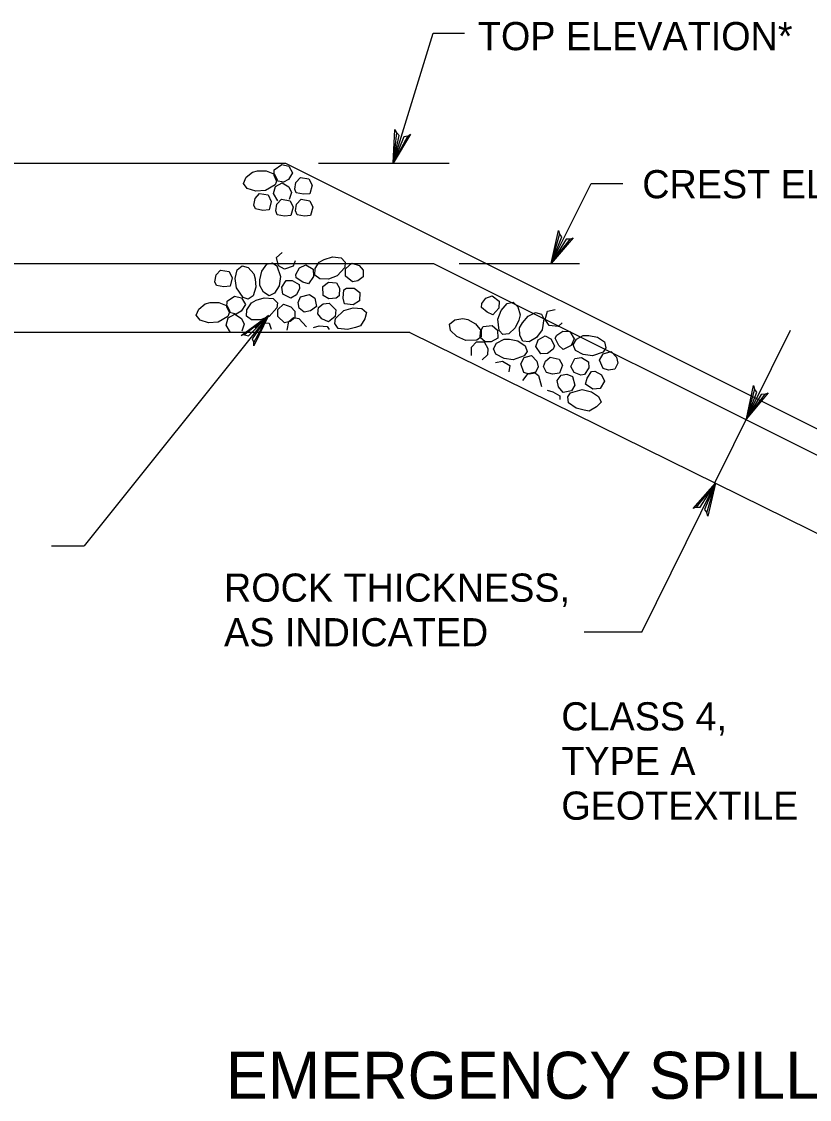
# Model space of a CAD drawing. Extents: x 636462 to 639890, y 299944 to 300538.
# Drawn here: x 637760.4 to 637844.1, y 300239.8 to 300354.4 of the extents above; entities that cross this region are included whole.
import ezdxf

# ---------------------------------------------------------------- set-up
doc = ezdxf.new("R2010")
doc.units = 0
doc.layers.add('Default', color=7, linetype='Continuous')

msp = doc.modelspace()

# ---------------------------------------------------------------- linework, layer by layer
at = {"layer": 'Default'}
for p, q in [((637799.86, 300339.34), (637804.11, 300353.17)), ((637804.11, 300353.17), (637807.46, 300353.17)), ((637706.06, 300339.34), (637788.44, 300339.34)), ((637788.44, 300339.34), (637929.75, 300268.68)), ((637791.92, 300339.34), (637805.8, 300339.34)), ((637784.24, 300337.85), (637784.93, 300338.41)), ((637784.93, 300338.41), (637785.44, 300338.53)), ((637785.44, 300338.53), (637786.38, 300338.54)), ((637786.38, 300338.54), (637787.26, 300338.17)), ((637787.22, 300338.05), (637787.24, 300338.66)), ((637787.24, 300338.66), (637788.03, 300339.21)), ((637788.03, 300339.21), (637788.77, 300339.03)), ((637789.19, 300338.32), (637788.75, 300337.63)), ((637788.77, 300339.03), (637789.19, 300338.32)), ((637783.96, 300337.18), (637784.24, 300337.85)), ((637784.37, 300336.65), (637783.96, 300337.18)), ((637787.33, 300337.06), (637786.29, 300336.46)), ((637787.49, 300337.48), (637787.22, 300338.05)), ((637787.26, 300338.17), (637787.55, 300337.61)), ((637787.55, 300337.61), (637787.33, 300337.06)), ((637787.36, 300336.89), (637788.08, 300337.28)), ((637788.2, 300337.32), (637787.49, 300337.48)), ((637788.08, 300337.28), (637788.77, 300336.85)), ((637788.75, 300337.63), (637788.2, 300337.32)), ((637789.41, 300336.59), (637789.52, 300337.31)), ((637789.52, 300337.31), (637790.01, 300337.83)), ((637790.01, 300337.83), (637790.92, 300337.68)), ((637790.92, 300337.68), (637791.25, 300337)), ((637816.66, 300328.69), (637820.91, 300337.19)), ((637820.91, 300337.19), (637824.26, 300337.19)), ((637785.27, 300336.39), (637784.37, 300336.65)), ((637785.19, 300335.6), (637785.68, 300336.13)), ((637786.29, 300336.46), (637785.27, 300336.39)), ((637785.68, 300336.13), (637786.59, 300335.98)), ((637786.59, 300335.98), (637786.92, 300335.29)), ((637787.16, 300336.14), (637787.36, 300336.89)), ((637787.6, 300335.36), (637787.16, 300336.14)), ((637788.77, 300336.85), (637789.05, 300336.23)), ((637789.05, 300336.23), (637788.81, 300335.5)), ((637789.57, 300336.19), (637789.41, 300336.59)), ((637790.35, 300336.05), (637789.57, 300336.19)), ((637791.01, 300336.11), (637790.35, 300336.05)), ((637791.25, 300337), (637791.01, 300336.11)), ((637785.08, 300334.88), (637785.19, 300335.6)), ((637785.24, 300334.49), (637785.08, 300334.88)), ((637786.92, 300335.29), (637786.68, 300334.4)), ((637787.4, 300334.27), (637787.51, 300334.99)), ((637787.51, 300334.99), (637788, 300335.51)), ((637788, 300335.51), (637788.91, 300335.36)), ((637788.91, 300335.36), (637789.24, 300334.68)), ((637789.5, 300334.27), (637789.61, 300334.99)), ((637789.61, 300334.99), (637790.1, 300335.51)), ((637790.1, 300335.51), (637791.01, 300335.36)), ((637791.01, 300335.36), (637791.34, 300334.68)), ((637786.02, 300334.34), (637785.24, 300334.49)), ((637786.68, 300334.4), (637786.02, 300334.34)), ((637787.56, 300333.87), (637787.4, 300334.27)), ((637788.34, 300333.73), (637787.56, 300333.87)), ((637789, 300333.79), (637788.34, 300333.73)), ((637789.24, 300334.68), (637789, 300333.79)), ((637789.66, 300333.87), (637789.5, 300334.27)), ((637790.44, 300333.73), (637789.66, 300333.87)), ((637791.1, 300333.79), (637790.44, 300333.73)), ((637791.34, 300334.68), (637791.1, 300333.79)), ((637787.48, 300329.31), (637788.09, 300329.86)), ((637787.68, 300328.45), (637787.48, 300329.31)), ((637792.02, 300328.84), (637792.55, 300329.13)), ((637792.55, 300329.13), (637793.44, 300329.4)), ((637793.44, 300329.4), (637794.34, 300329.3)), ((637794.34, 300329.3), (637794.77, 300328.83)), ((637684.74, 300328.68), (637804.15, 300328.68)), ((637781.05, 300327.47), (637781.54, 300327.99)), ((637781.54, 300327.99), (637782.45, 300327.84)), ((637783.09, 300327.08), (637783.31, 300328.02)), ((637783.31, 300328.02), (637783.81, 300328.44)), ((637783.81, 300328.44), (637784.47, 300328.26)), ((637784.47, 300328.26), (637785.08, 300327.59)), ((637785.9, 300327.87), (637786.43, 300328.61)), ((637786.43, 300328.61), (637787.05, 300328.75)), ((637787.05, 300328.75), (637787.51, 300328.44)), ((637787.51, 300328.44), (637787.89, 300327.3)), ((637788.34, 300328.07), (637787.68, 300328.45)), ((637789.26, 300328.42), (637788.34, 300328.07)), ((637789.44, 300328.97), (637789.26, 300328.42)), ((637789.54, 300327.53), (637789.91, 300328.24)), ((637789.91, 300328.24), (637790.6, 300328.54)), ((637790.6, 300328.54), (637791.37, 300328.08)), ((637791.37, 300328.08), (637791.42, 300327.29)), ((637791.55, 300327.45), (637791.59, 300328.15)), ((637791.59, 300328.15), (637792.02, 300328.84)), ((637794.72, 300328.27), (637793.92, 300327.38)), ((637794.77, 300328.83), (637794.72, 300328.27)), ((637794.8, 300327.36), (637794.81, 300328.12)), ((637794.81, 300328.12), (637795.47, 300328.72)), ((637795.47, 300328.72), (637796.24, 300328.46)), ((637796.24, 300328.46), (637796.67, 300327.99)), ((637796.67, 300327.99), (637796.69, 300327.27)), ((637804.16, 300328.69), (637929.74, 300265.89)), ((637806.87, 300328.69), (637819.67, 300328.69)), ((637780.94, 300326.75), (637781.05, 300327.47)), ((637781.09, 300326.35), (637780.94, 300326.75)), ((637782.45, 300327.84), (637782.78, 300327.16)), ((637782.78, 300327.16), (637782.54, 300326.27)), ((637783.23, 300326.1), (637783.09, 300327.08)), ((637785.08, 300327.59), (637785.22, 300327.06)), ((637785.22, 300327.06), (637785.28, 300326.16)), ((637785.7, 300326.96), (637785.9, 300327.87)), ((637785.7, 300326.36), (637785.7, 300326.96)), ((637787.89, 300327.3), (637787.75, 300326.32)), ((637788.03, 300326.16), (637788.5, 300326.9)), ((637788.5, 300326.9), (637789.15, 300326.89)), ((637789.15, 300326.89), (637789.87, 300326.44)), ((637789.55, 300327.18), (637789.54, 300327.53)), ((637790.26, 300326.7), (637789.55, 300327.18)), ((637791.42, 300327.29), (637790.87, 300326.52)), ((637792.07, 300327.06), (637791.55, 300327.45)), ((637792.99, 300327.03), (637792.07, 300327.06)), ((637793.92, 300327.38), (637792.99, 300327.03)), ((637795.56, 300326.73), (637794.8, 300327.36)), ((637796.13, 300326.85), (637795.56, 300326.73)), ((637796.69, 300327.27), (637796.13, 300326.85)), ((637781.88, 300326.21), (637781.09, 300326.35)), ((637782.54, 300326.27), (637781.88, 300326.21)), ((637783.92, 300325.09), (637783.23, 300326.1)), ((637785.28, 300326.16), (637785, 300325.25)), ((637786.09, 300325.65), (637785.7, 300326.36)), ((637786.68, 300325.27), (637786.09, 300325.65)), ((637787.75, 300326.32), (637787.27, 300325.53)), ((637788.15, 300325.44), (637788.03, 300326.16)), ((637789.91, 300326.04), (637789.6, 300325.36)), ((637789.87, 300326.44), (637789.91, 300326.04)), ((637790.87, 300326.52), (637790.26, 300326.7)), ((637792.41, 300326.25), (637792.98, 300326.71)), ((637792.43, 300325.3), (637792.41, 300326.25)), ((637792.98, 300326.71), (637793.86, 300326.65)), ((637793.86, 300326.65), (637794.17, 300326.08)), ((637794.17, 300326.08), (637794.13, 300325.24)), ((637794.55, 300325.02), (637794.61, 300325.88)), ((637794.61, 300325.88), (637794.91, 300326.06)), ((637794.91, 300326.06), (637795.72, 300326.08)), ((637795.72, 300326.08), (637796.31, 300325.62)), ((637796.31, 300325.62), (637796.29, 300324.73)), ((637779.91, 300324.42), (637780.42, 300324.53)), ((637780.42, 300324.53), (637781.36, 300324.55)), ((637781.36, 300324.55), (637782.25, 300324.18)), ((637782.21, 300324.06), (637782.22, 300324.67)), ((637782.22, 300324.67), (637783.01, 300325.21)), ((637783.01, 300325.21), (637783.75, 300325.03)), ((637783.75, 300325.03), (637784.17, 300324.33)), ((637784.46, 300324.89), (637783.92, 300325.09)), ((637784.31, 300323.78), (637784.82, 300324.52)), ((637785, 300325.25), (637784.46, 300324.89)), ((637784.82, 300324.52), (637785.31, 300324.78)), ((637785.31, 300324.78), (637786.17, 300325.04)), ((637786.17, 300325.04), (637787.12, 300324.97)), ((637787.27, 300325.53), (637786.68, 300325.27)), ((637787.12, 300324.97), (637787.59, 300324.52)), ((637787.59, 300324.52), (637787.52, 300323.96)), ((637788.99, 300324.99), (637788.15, 300325.44)), ((637789.6, 300325.36), (637788.99, 300324.99)), ((637789.78, 300324.54), (637790.03, 300325.14)), ((637789.87, 300323.94), (637789.78, 300324.54)), ((637790.03, 300325.14), (637790.98, 300325.4)), ((637790.98, 300325.4), (637791.56, 300325.02)), ((637791.56, 300325.02), (637791.71, 300324.12)), ((637792.42, 300324.39), (637793.08, 300324.46)), ((637793.05, 300324.94), (637792.43, 300325.3)), ((637793.8, 300325.01), (637793.05, 300324.94)), ((637793.08, 300324.46), (637793.76, 300323.76)), ((637794.13, 300325.24), (637793.8, 300325.01)), ((637794.68, 300324.4), (637794.55, 300325.02)), ((637796.29, 300324.73), (637795.62, 300324.3)), ((637809.29, 300324.43), (637809.72, 300325.01)), ((637809.72, 300325.01), (637810.4, 300325.25)), ((637810.4, 300325.25), (637811.14, 300324.68)), ((637811.14, 300324.68), (637811.1, 300323.93)), ((637811.98, 300324.43), (637812.61, 300324.57)), ((637812.61, 300324.57), (637813.11, 300324.1)), ((637778.94, 300323.19), (637779.23, 300323.85)), ((637779.23, 300323.85), (637779.91, 300324.42)), ((637782.47, 300323.49), (637782.21, 300324.06)), ((637782.25, 300324.18), (637782.53, 300323.61)), ((637782.53, 300323.61), (637782.32, 300323.07)), ((637783.18, 300323.32), (637782.47, 300323.49)), ((637783.73, 300323.63), (637783.18, 300323.32)), ((637784.17, 300324.33), (637783.73, 300323.63)), ((637784.28, 300323.09), (637784.31, 300323.78)), ((637787.52, 300323.96), (637786.7, 300323.05)), ((637787.6, 300323.04), (637787.61, 300323.81)), ((637787.61, 300323.81), (637788.21, 300324.37)), ((637788.21, 300324.37), (637788.98, 300324.1)), ((637788.98, 300324.1), (637789.41, 300323.63)), ((637789.41, 300323.63), (637789.41, 300322.9)), ((637790.43, 300323.53), (637789.87, 300323.94)), ((637791.1, 300323.65), (637790.43, 300323.53)), ((637791.71, 300324.12), (637791.1, 300323.65)), ((637791.86, 300323.33), (637791.94, 300324.01)), ((637792.3, 300322.8), (637791.86, 300323.33)), ((637791.94, 300324.01), (637792.42, 300324.39)), ((637793.76, 300323.76), (637793.71, 300323.06)), ((637793.73, 300322.84), (637794.63, 300323.71)), ((637794.63, 300323.71), (637795.63, 300323.98)), ((637795.62, 300324.3), (637794.68, 300324.4)), ((637795.63, 300323.98), (637796.54, 300323.89)), ((637796.54, 300323.89), (637797.05, 300323.47)), ((637797.05, 300323.47), (637796.87, 300322.8)), ((637809.24, 300324.01), (637809.29, 300324.43)), ((637809.86, 300323.51), (637809.24, 300324.01)), ((637810.47, 300323.25), (637809.86, 300323.51)), ((637811.1, 300323.93), (637810.47, 300323.25)), ((637811, 300322.78), (637811.34, 300323.71)), ((637811.34, 300323.71), (637811.98, 300324.43)), ((637813.11, 300324.1), (637813.34, 300323.22)), ((637814.19, 300323.08), (637815, 300323.48)), ((637815, 300323.48), (637815.62, 300323.32)), ((637815.62, 300323.32), (637815.88, 300322.82)), ((637816.03, 300322.75), (637816.27, 300323.61)), ((637816.27, 300323.61), (637817.06, 300323.8)), ((637786.63, 300323.18), (637767.06, 300298.69)), ((637779.35, 300322.66), (637778.94, 300323.19)), ((637780.25, 300322.4), (637779.35, 300322.66)), ((637781.28, 300322.47), (637780.25, 300322.4)), ((637782.32, 300323.07), (637781.28, 300322.47)), ((637782.14, 300322.15), (637782.35, 300322.9)), ((637782.58, 300321.37), (637782.14, 300322.15)), ((637782.35, 300322.9), (637783.06, 300323.29)), ((637783.06, 300323.29), (637783.75, 300322.85)), ((637783.75, 300322.85), (637784.03, 300322.23)), ((637784.03, 300322.23), (637783.8, 300321.5)), ((637784.81, 300322.71), (637784.28, 300323.09)), ((637785.77, 300322.7), (637784.81, 300322.71)), ((637785.17, 300321.9), (637785.76, 300322.38)), ((637785.76, 300322.38), (637786.68, 300322.35)), ((637786.7, 300323.05), (637785.77, 300322.7)), ((637786.68, 300322.35), (637786.89, 300321.71)), ((637788.31, 300322.39), (637787.6, 300323.04)), ((637788.91, 300322.52), (637788.31, 300322.39)), ((637788.62, 300321.59), (637788.79, 300322.53)), ((637788.79, 300322.53), (637789.27, 300322.94)), ((637789.41, 300322.9), (637788.91, 300322.52)), ((637789.27, 300322.94), (637789.85, 300322.85)), ((637789.85, 300322.85), (637790.67, 300321.97)), ((637793, 300322.49), (637792.3, 300322.8)), ((637793.71, 300323.06), (637793, 300322.49)), ((637793.67, 300322.31), (637793.73, 300322.84)), ((637794.04, 300321.78), (637793.67, 300322.31)), ((637796.87, 300322.8), (637796.39, 300322.05)), ((637805.85, 300322.23), (637806.41, 300322.69)), ((637805.96, 300321.58), (637805.85, 300322.23)), ((637806.41, 300322.69), (637807.28, 300322.86)), ((637807.28, 300322.86), (637807.79, 300322.72)), ((637807.79, 300322.72), (637808.62, 300322.29)), ((637808.62, 300322.29), (637809.23, 300321.55)), ((637811.13, 300321.56), (637811, 300322.78)), ((637813.21, 300322.68), (637812.84, 300321.86)), ((637813.34, 300323.22), (637813.21, 300322.68)), ((637813.3, 300321.84), (637813.59, 300322.37)), ((637813.59, 300322.37), (637814.19, 300323.08)), ((637815.88, 300322.82), (637815.68, 300321.64)), ((637816.44, 300322.1), (637816.03, 300322.75)), ((637817.83, 300322.38), (637817.41, 300321.98)), ((637801.63, 300321.37), (637728.01, 300321.37)), ((637791.41, 300321.89), (637792.02, 300322.05)), ((637792.02, 300322.05), (637792.86, 300322)), ((637792.86, 300322), (637793.07, 300321.66)), ((637795, 300321.68), (637794.04, 300321.78)), ((637795.87, 300321.88), (637795, 300321.68)), ((637796.39, 300322.05), (637795.87, 300321.88)), ((637801.63, 300321.37), (637927.67, 300259.18)), ((637806.63, 300320.92), (637805.96, 300321.58)), ((637809.1, 300320.83), (637809.14, 300321.46)), ((637809.14, 300321.46), (637809.43, 300321.99)), ((637809.23, 300321.55), (637809.22, 300320.91)), ((637809.43, 300321.99), (637810.39, 300322.1)), ((637810.39, 300322.1), (637810.96, 300321.59)), ((637810.96, 300321.59), (637810.99, 300320.77)), ((637811.51, 300321.14), (637811.13, 300321.56)), ((637812.16, 300321.2), (637811.51, 300321.14)), ((637812.84, 300321.86), (637812.16, 300321.2)), ((637813.31, 300321.03), (637813.3, 300321.84)), ((637813.65, 300320.42), (637813.31, 300321.03)), ((637815.68, 300321.64), (637815.09, 300320.84)), ((637817.41, 300321.98), (637816.44, 300322.1)), ((637817.08, 300320.75), (637817.24, 300321.06)), ((637817.24, 300321.06), (637817.9, 300321.51)), ((637817.9, 300321.51), (637818.65, 300321.45)), ((637818.65, 300321.45), (637819.11, 300320.69)), ((637819.34, 300320.64), (637820.05, 300321.05)), ((637820.05, 300321.05), (637820.65, 300321.05)), ((637820.65, 300321.05), (637821.56, 300320.87)), ((637834.03, 300305.39), (637842.06, 300321.62)), ((637807.57, 300320.5), (637806.63, 300320.92)), ((637808.77, 300320.54), (637807.57, 300320.5)), ((637808.18, 300319.81), (637808.71, 300320.37)), ((637808.71, 300320.37), (637809.52, 300320.38)), ((637809.22, 300320.91), (637808.77, 300320.54)), ((637809.65, 300320.35), (637809.1, 300320.83)), ((637809.52, 300320.38), (637809.93, 300319.67)), ((637810.28, 300320.37), (637809.65, 300320.35)), ((637810.99, 300320.77), (637810.28, 300320.37)), ((637810.51, 300319.63), (637810.86, 300320.22)), ((637810.86, 300320.22), (637811.66, 300320.64)), ((637811.66, 300320.64), (637812.21, 300320.64)), ((637812.21, 300320.64), (637813.1, 300320.46)), ((637813.1, 300320.46), (637813.9, 300319.94)), ((637814.3, 300320.37), (637813.65, 300320.42)), ((637813.9, 300319.94), (637814.1, 300319.33)), ((637815.09, 300320.84), (637814.3, 300320.37)), ((637815.03, 300319.87), (637815.26, 300320.57)), ((637815.55, 300319.08), (637815.03, 300319.87)), ((637815.26, 300320.57), (637816.03, 300320.99)), ((637816.03, 300320.99), (637816.6, 300320.68)), ((637816.6, 300320.68), (637817.02, 300319.95)), ((637817.02, 300319.95), (637816.86, 300319.58)), ((637817.48, 300319.99), (637817.08, 300320.75)), ((637817.93, 300319.55), (637817.48, 300319.99)), ((637818.78, 300319.96), (637817.93, 300319.55)), ((637819.11, 300320.69), (637818.78, 300319.96)), ((637818.97, 300320.04), (637819.34, 300320.64)), ((637819.25, 300319.46), (637818.97, 300320.04)), ((637821.56, 300320.87), (637822.31, 300320.36)), ((637822.31, 300320.36), (637822.46, 300319.74)), ((637808.2, 300318.91), (637808.18, 300319.81)), ((637809.88, 300318.99), (637809.33, 300318.46)), ((637809.93, 300319.67), (637809.88, 300318.99)), ((637810.79, 300319.04), (637810.51, 300319.63)), ((637811.64, 300318.58), (637810.79, 300319.04)), ((637813.78, 300318.86), (637812.62, 300318.46)), ((637814.1, 300319.33), (637813.78, 300318.86)), ((637813.78, 300318.69), (637814.57, 300318.9)), ((637814.57, 300318.9), (637815.13, 300318.3)), ((637816.27, 300319.12), (637815.55, 300319.08)), ((637816.04, 300318.31), (637816.55, 300318.73)), ((637816.86, 300319.58), (637816.27, 300319.12)), ((637816.55, 300318.73), (637817.5, 300318.51)), ((637819.17, 300318.58), (637819.89, 300318.71)), ((637820.05, 300319), (637819.25, 300319.46)), ((637819.89, 300318.71), (637820.63, 300318.25)), ((637821.03, 300318.87), (637820.05, 300319)), ((637822.16, 300319.27), (637821.03, 300318.87)), ((637821.8, 300318.43), (637822.17, 300319.1)), ((637822.46, 300319.74), (637822.16, 300319.27)), ((637822.17, 300319.1), (637823.03, 300319.32)), ((637823.03, 300319.32), (637823.59, 300318.72)), ((637823.59, 300318.72), (637823.74, 300318.1)), ((637810.73, 300318.16), (637811.48, 300318.3)), ((637811.48, 300318.3), (637812.27, 300317.84)), ((637812.62, 300318.46), (637811.64, 300318.58)), ((637812.27, 300317.84), (637812.16, 300317.18)), ((637813.42, 300318.02), (637813.78, 300318.69)), ((637813.74, 300317.11), (637813.42, 300318.02)), ((637815.28, 300317.69), (637814.94, 300317.04)), ((637815.13, 300318.3), (637815.28, 300317.69)), ((637815.84, 300317.74), (637816.04, 300318.31)), ((637816.14, 300317.12), (637815.84, 300317.74)), ((637817.5, 300318.51), (637817.84, 300317.89)), ((637817.84, 300317.89), (637817.55, 300317.03)), ((637818.73, 300317.73), (637819.17, 300318.58)), ((637819.11, 300317.12), (637818.73, 300317.73)), ((637820.64, 300317.6), (637820.2, 300316.88)), ((637820.63, 300318.25), (637820.64, 300317.6)), ((637822.17, 300317.52), (637821.8, 300318.43)), ((637823.74, 300318.1), (637823.42, 300317.46)), ((637813.63, 300316.25), (637814.22, 300317.01)), ((637814.32, 300316.94), (637813.74, 300317.11)), ((637814.22, 300317.01), (637814.84, 300317.14)), ((637814.94, 300317.04), (637814.32, 300316.94)), ((637814.84, 300317.14), (637815.3, 300316.79)), ((637815.3, 300316.79), (637815.61, 300315.63)), ((637816.79, 300316.91), (637816.14, 300317.12)), ((637817.55, 300317.03), (637816.79, 300316.91)), ((637817.3, 300316.26), (637817.7, 300316.83)), ((637817.7, 300316.83), (637818.3, 300316.93)), ((637818.3, 300316.93), (637818.91, 300316.69)), ((637818.91, 300316.69), (637819.18, 300315.75)), ((637819.8, 300316.83), (637819.11, 300317.12)), ((637820.2, 300316.88), (637819.8, 300316.83)), ((637820.3, 300315.88), (637820.47, 300316.49)), ((637820.47, 300316.49), (637820.94, 300317.21)), ((637820.94, 300317.21), (637821.28, 300317.23)), ((637821.28, 300317.23), (637822, 300316.86)), ((637822, 300316.86), (637822.31, 300316.18)), ((637822.73, 300317.35), (637822.17, 300317.52)), ((637823.42, 300317.46), (637822.73, 300317.35)), ((637817.44, 300315.59), (637817.3, 300316.26)), ((637817.92, 300314.99), (637817.44, 300315.59)), ((637818.72, 300314.95), (637819.93, 300315.29)), ((637819.18, 300315.75), (637818.81, 300315.16)), ((637819.93, 300315.29), (637820.94, 300315.06)), ((637821.08, 300315.34), (637820.3, 300315.88)), ((637821.87, 300315.41), (637821.08, 300315.34)), ((637822.31, 300316.18), (637821.87, 300315.41)), ((637816.23, 300315.21), (637816.84, 300315.06)), ((637816.84, 300315.06), (637817.56, 300314.62)), ((637817.56, 300314.62), (637817.58, 300314.22)), ((637818.81, 300315.16), (637817.92, 300314.99)), ((637818.42, 300314.51), (637818.72, 300314.95)), ((637818.5, 300313.87), (637818.42, 300314.51)), ((637820.94, 300315.06), (637821.69, 300314.55)), ((637821.69, 300314.55), (637821.95, 300313.94)), ((637819.3, 300313.33), (637818.5, 300313.87)), ((637820.16, 300313.1), (637819.3, 300313.33)), ((637820.69, 300313), (637820.16, 300313.1)), ((637821.47, 300313.44), (637820.69, 300313)), ((637821.95, 300313.94), (637821.47, 300313.44)), ((637826.28, 300289.5), (637834.12, 300305.34)), ((637763.56, 300298.69), (637767.06, 300298.69)), ((637826.28, 300289.5), (637820.16, 300289.5))]:
    msp.add_line(p, q, dxfattribs=at)
for points in [[(637801.43, 300342.24), (637801.72, 300342.43), (637799.86, 300339.34), (637801.43, 300342.24), (637801.01, 300342.16), (637799.86, 300339.34), (637800.51, 300342.31), (637800.21, 300342.6), (637799.86, 300339.34), (637800.05, 300342.94), (637800.21, 300342.6)], [(637818.68, 300331.29), (637819, 300331.43), (637816.66, 300328.69), (637818.68, 300331.29), (637818.26, 300331.28), (637816.66, 300328.69), (637817.79, 300331.51), (637817.54, 300331.84), (637816.66, 300328.69), (637817.44, 300332.21), (637817.54, 300331.84)], [(637784.08, 300321.1), (637783.73, 300321.04), (637786.63, 300323.18), (637784.08, 300321.1), (637784.49, 300321.01), (637786.63, 300323.18), (637784.89, 300320.68), (637785.07, 300320.3), (637786.63, 300323.18), (637785.08, 300319.93), (637785.07, 300320.3)], [(637839.39, 300314.79), (637839.71, 300314.94), (637837.39, 300312.18), (637839.39, 300314.79), (637838.97, 300314.78), (637837.39, 300312.18), (637838.5, 300315.01), (637838.25, 300315.34), (637837.39, 300312.18), (637838.14, 300315.71), (637838.25, 300315.34)], [(637832.05, 300302.78), (637831.73, 300302.64), (637834.12, 300305.34), (637832.05, 300302.78), (637832.47, 300302.78), (637834.12, 300305.34), (637832.94, 300302.54), (637833.18, 300302.2), (637834.12, 300305.34), (637833.28, 300301.83), (637833.18, 300302.2)]]:
    msp.add_lwpolyline(points, dxfattribs=at)

# ---------------------------------------------------------------- texts
for s, height, p in [('TOP ELEVATION*', 2.998, (637808.87, 300351.36)), ('CREST ELEVATION*', 2.998, (637826.33, 300335.62)), ('ROCK THICKNESS,', 2.998, (637781.9, 300292.74)), ('AS INDICATED', 2.998, (637781.9, 300288)), ('CLASS 4,', 2.998, (637817.73, 300279.06)), ('TYPE A', 2.998, (637817.73, 300274.31)), ('GEOTEXTILE', 2.998, (637817.73, 300269.57)), ('EMERGENCY SPILLWAY', 4.9967, (637782.1, 300239.91))]:
    msp.add_text(s, height=height, dxfattribs=at).set_placement(p)

doc.saveas('drawing.dxf')
